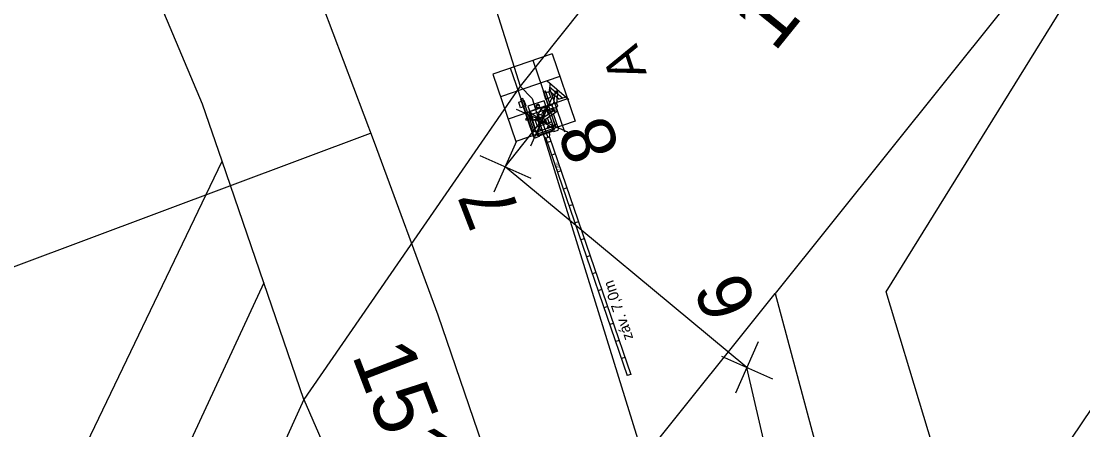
# Model space of a CAD drawing. Extents: x -553916 to -552953, y -1067470 to -1066637.
# Drawn here: x -553527.29 to -553497.63, y -1066980.55 to -1066969.15 of the extents above; entities that cross this region are included whole.
import ezdxf

# ---------------------------------------------------------------- set-up
doc = ezdxf.new("R2010")
doc.units = 0
for name, color, linetype in [('Default', 7, 'Continuous'), ('El2015-Ochrana podzemní', 7, 'Continuous'), ('El2015-Zabzař podzemní', 7, 'Continuous'), ('Hranice parcel', 7, 'Continuous'), ('Kolej', 7, 'Continuous'), ('Nová kabelizace', 7, 'Continuous'), ('nové prvky ZZ', 7, 'Continuous'), ('Parcelní čísla', 7, 'Continuous'), ('Propustek', 7, 'Continuous'), ('trasa_NN_popisky', 7, 'Continuous'), ('Vrstva 1', 7, 'Continuous')]:
    doc.layers.add(name, color=color, linetype=linetype)

# ---------------------------------------------------------------- blocks, each defined once
blk = doc.blocks.new('Křížek')
at = {"layer": 'El2015-Zabzař podzemní'}
for p, q in [((8.84, -8.84), (-8.84, 8.84)), ((8.84, -8.84), (-8.84, 8.84)), ((8.84, -8.84), (-8.84, 8.84)), ((8.84, 8.84), (-8.84, -8.84))]:
    blk.add_line(p, q, dxfattribs=at)

msp = doc.modelspace()

# ---------------------------------------------------------------- linework, layer by layer
at = {"layer": 'Hranice parcel'}
for p, q in [((-553499.93, -1066968.9), (-553506.23, -1066976.75)), ((-553520.52, -1066976.45), (-553530.98, -1066998.99)), ((-553519.4, -1066979.7), (-553528.66, -1067000.03))]:
    msp.add_line(p, q, dxfattribs=at)
for points in [[(-553489.9, -1066939.2), (-553506.21, -1066961.59), (-553507.62, -1066963.64), (-553510.49, -1066967.37), (-553513.35, -1066970.96)], [(-553481.25, -1066991.64), (-553501.02, -1066983.66), (-553503.13, -1066976.7), (-553485.37, -1066948.09)], [(-553533.63, -1066998.28), (-553526.12, -1066982.3), (-553521.68, -1066973.05)]]:
    msp.add_lwpolyline(points, dxfattribs=at)
at = {"layer": 'Kolej'}
msp.add_lwpolyline([(-553503.324, -1067065.808), (-553502.678, -1067054.027), (-553502.762, -1067041.504), (-553503.626, -1067029.057), (-553504.756, -1067019.974), (-553506.183, -1067011.388), (-553508.328, -1067001.388), (-553510.948, -1066991.622), (-553512.921, -1066985.291), (-553515.647, -1066977.347), (-553517.422, -1066972.53), (-553519.157, -1066967.95), (-553522.886, -1066958.375), (-553529.101, -1066942.549), (-553538.686, -1066918.107), (-553542.908, -1066907.329), (-553546.692, -1066897.676), (-553555.025, -1066876.441), (-553564.644, -1066851.894), (-553574.241, -1066827.427), (-553583.19, -1066804.618)], dxfattribs=at)
at = {"layer": 'Nová kabelizace'}
msp.add_line((-553505.478, -1066985.448), (-553507.017, -1066978.813), dxfattribs=at)
msp.add_lwpolyline([(-553507.017, -1066978.813), (-553513.769, -1066973.209), (-553512.749, -1066971.917)], dxfattribs=at)
at = {"layer": 'nové prvky ZZ'}
for p, q in [((-553512.461, -1066970.063), (-553514.116, -1066970.631)), ((-553512.349, -1066972.124), (-553512.993, -1066970.246)), ((-553512.461, -1066970.063), (-553511.816, -1066971.941)), ((-553514.116, -1066970.631), (-553513.471, -1066972.509)), ((-553512.975, -1066972.339), (-553513.62, -1066970.461)), ((-553512.246, -1066970.689), (-553513.901, -1066971.257)), ((-553512.595, -1066970.814), (-553511.991, -1066971.338)), ((-553512.52, -1066970.88), (-553512.54, -1066971.079)), ((-553512.7, -1066971.109), (-553512.644, -1066971.09)), ((-553512.56, -1066971.518), (-553512.7, -1066971.109)), ((-553512.504, -1066971.499), (-553512.644, -1066971.09)), ((-553512.54, -1066971.079), (-553512.261, -1066971.321)), ((-553512.53, -1066970.979), (-553512.163, -1066971.297)), ((-553512.528, -1066971.045), (-553512.119, -1066972.237)), ((-553512.385, -1066971.135), (-553512.421, -1066971.443)), ((-553512.293, -1066971.076), (-553512.4, -1066971.2)), ((-553512.355, -1066971.139), (-553512.338, -1066971.137)), ((-553512.345, -1066971.146), (-553512.348, -1066971.13)), ((-553512.306, -1066971.145), (-553512.341, -1066971.451)), ((-553512.031, -1066971.315), (-553513.686, -1066971.883)), ((-553513.282, -1066971.308), (-553513.337, -1066971.328)), ((-553512.971, -1066972.394), (-553513.337, -1066971.328)), ((-553512.964, -1066972.234), (-553513.282, -1066971.308)), ((-553513.106, -1066971.666), (-553512.624, -1066971.499)), ((-553513.05, -1066971.646), (-553512.624, -1066971.499)), ((-553512.91, -1066971.521), (-553512.912, -1066971.522)), ((-553512.875, -1066972.337), (-553512.624, -1066971.499)), ((-553512.453, -1066971.481), (-553512.775, -1066971.592)), ((-553512.393, -1066972.17), (-553512.624, -1066971.499)), ((-553512.066, -1066971.273), (-553512.261, -1066971.321)), ((-553512.875, -1066972.337), (-553513.105, -1066971.665)), ((-553513.105, -1066971.665), (-553512.393, -1066972.17)), ((-553513.079, -1066971.816), (-553513.058, -1066971.878)), ((-553513.056, -1066971.755), (-553513.007, -1066971.899)), ((-553513.043, -1066971.751), (-553512.993, -1066971.897)), ((-553512.775, -1066971.592), (-553512.853, -1066971.748)), ((-553512.853, -1066971.748), (-553512.811, -1066971.868)), ((-553512.853, -1066971.748), (-553512.757, -1066971.756)), ((-553512.8, -1066971.856), (-553512.763, -1066971.83)), ((-553512.775, -1066971.592), (-553512.713, -1066971.663)), ((-553512.759, -1066971.82), (-553512.743, -1066971.808)), ((-553512.713, -1066971.663), (-553512.757, -1066971.756)), ((-553512.757, -1066971.756), (-553512.734, -1066971.823)), ((-553512.73, -1066971.829), (-553512.746, -1066971.84)), ((-553512.743, -1066971.808), (-553512.73, -1066971.829)), ((-553512.736, -1066971.818), (-553512.591, -1066971.768)), ((-553512.731, -1066971.828), (-553512.628, -1066971.793)), ((-553512.731, -1066971.83), (-553512.725, -1066971.849)), ((-553512.377, -1066971.624), (-553512.717, -1066971.853)), ((-553512.713, -1066971.663), (-553512.427, -1066971.565)), ((-553512.336, -1066971.681), (-553512.677, -1066971.91)), ((-553512.609, -1066971.628), (-553512.567, -1066971.752)), ((-553512.587, -1066971.659), (-553512.557, -1066971.745)), ((-553512.557, -1066971.744), (-553512.552, -1066971.733)), ((-553512.496, -1066971.704), (-553512.531, -1066971.601)), ((-553512.47, -1066971.957), (-553512.522, -1066971.806)), ((-553512.506, -1066971.675), (-553512.469, -1066971.663)), ((-553512.445, -1066971.67), (-553512.476, -1066971.582)), ((-553512.383, -1066972.035), (-553512.472, -1066971.773)), ((-553512.469, -1066971.663), (-553512.461, -1066971.657)), ((-553512.461, -1066971.657), (-553512.454, -1066971.644)), ((-553512.422, -1066971.607), (-553512.434, -1066971.611)), ((-553512.411, -1066971.64), (-553512.423, -1066971.644)), ((-553512.421, -1066971.611), (-553512.422, -1066971.607)), ((-553512.278, -1066972.156), (-553512.422, -1066971.738)), ((-553512.414, -1066971.609), (-553512.421, -1066971.611)), ((-553512.414, -1066971.609), (-553512.405, -1066971.633)), ((-553512.405, -1066971.633), (-553512.412, -1066971.636)), ((-553512.412, -1066971.636), (-553512.411, -1066971.64)), ((-553511.816, -1066971.941), (-553513.471, -1066972.509)), ((-553513.201, -1066971.879), (-553513.194, -1066971.877)), ((-553513.201, -1066971.879), (-553513.192, -1066971.903)), ((-553513.195, -1066971.873), (-553513.183, -1066971.869)), ((-553513.194, -1066971.877), (-553513.195, -1066971.873)), ((-553513.192, -1066971.903), (-553513.185, -1066971.901)), ((-553513.185, -1066971.901), (-553513.184, -1066971.905)), ((-553513.184, -1066971.905), (-553513.172, -1066971.901)), ((-553513.134, -1066971.888), (-553513.147, -1066971.882)), ((-553513.124, -1066971.888), (-553513.134, -1066971.888)), ((-553513.087, -1066971.875), (-553513.124, -1066971.888)), ((-553513.021, -1066971.894), (-553512.944, -1066972.12)), ((-553513.007, -1066971.899), (-553512.995, -1066971.912)), ((-553512.995, -1066971.912), (-553512.977, -1066971.913)), ((-553512.993, -1066971.897), (-553512.98, -1066971.902)), ((-553512.98, -1066971.902), (-553512.819, -1066971.846)), ((-553512.977, -1066971.913), (-553512.815, -1066971.857)), ((-553512.944, -1066972.12), (-553512.874, -1066972.096)), ((-553512.871, -1066972.089), (-553512.936, -1066971.899)), ((-553512.907, -1066971.888), (-553512.898, -1066971.914)), ((-553512.898, -1066971.914), (-553512.891, -1066971.922)), ((-553512.895, -1066971.884), (-553512.885, -1066971.916)), ((-553512.891, -1066971.922), (-553512.882, -1066971.927)), ((-553512.885, -1066971.916), (-553512.876, -1066971.916)), ((-553512.882, -1066971.927), (-553512.873, -1066971.927)), ((-553512.876, -1066971.916), (-553512.85, -1066971.907)), ((-553512.876, -1066972.091), (-553512.871, -1066972.089)), ((-553512.874, -1066972.096), (-553512.876, -1066972.091)), ((-553512.873, -1066971.927), (-553512.84, -1066971.916)), ((-553512.871, -1066972.089), (-553512.546, -1066971.978)), ((-553512.851, -1066971.92), (-553512.83, -1066971.981)), ((-553512.842, -1066971.911), (-553512.819, -1066971.977)), ((-553512.717, -1066971.906), (-553512.782, -1066971.929)), ((-553512.769, -1066971.848), (-553512.757, -1066971.84)), ((-553512.76, -1066971.885), (-553512.738, -1066971.95)), ((-553512.745, -1066971.916), (-553512.754, -1066971.919)), ((-553512.748, -1066971.922), (-553512.751, -1066971.913)), ((-553512.749, -1066971.917), (-553512.585, -1066972.397)), ((-553512.71, -1066971.986), (-553512.674, -1066971.964)), ((-553512.693, -1066971.963), (-553512.681, -1066971.955)), ((-553512.658, -1066971.931), (-553512.677, -1066971.944)), ((-553512.673, -1066971.908), (-553512.668, -1066971.925)), ((-553512.664, -1066971.964), (-553512.645, -1066971.951)), ((-553512.663, -1066971.901), (-553512.656, -1066971.921)), ((-553512.645, -1066971.951), (-553512.658, -1066971.931)), ((-553512.546, -1066971.978), (-553512.589, -1066971.851)), ((-553512.541, -1066971.976), (-553512.546, -1066971.978)), ((-553512.539, -1066971.981), (-553512.541, -1066971.976)), ((-553512.47, -1066971.957), (-553512.539, -1066971.981)), ((-553512.468, -1066972.064), (-553512.349, -1066972.023)), ((-553512.456, -1066972.097), (-553512.468, -1066972.064)), ((-553512.349, -1066972.023), (-553512.319, -1066972.037)), ((-553512.998, -1066972.246), (-553513.012, -1066972.274)), ((-553512.879, -1066972.205), (-553512.998, -1066972.246)), ((-553512.942, -1066972.408), (-553512.971, -1066972.394)), ((-553512.823, -1066972.367), (-553512.942, -1066972.408)), ((-553512.867, -1066972.238), (-553512.879, -1066972.205)), ((-553512.875, -1066972.337), (-553512.393, -1066972.17)), ((-553512.829, -1066972.35), (-553512.823, -1066972.367)), ((-553512.548, -1066972.254), (-553512.705, -1066972.308)), ((-553512.538, -1066972.381), (-553512.632, -1066972.413)), ((-553512.632, -1066972.413), (-553510.36, -1066979.034)), ((-553512.538, -1066972.381), (-553510.266, -1066979.002)), ((-553512.418, -1066972.209), (-553512.412, -1066972.226)), ((-553512.412, -1066972.226), (-553512.293, -1066972.185)), ((-553512.293, -1066972.185), (-553512.278, -1066972.156)), ((-553512.593, -1066972.525), (-553512.499, -1066972.493)), ((-553512.375, -1066972.854), (-553512.469, -1066972.886)), ((-553512.213, -1066973.327), (-553512.307, -1066973.359)), ((-553512.051, -1066973.8), (-553512.145, -1066973.832)), ((-553511.889, -1066974.273), (-553511.983, -1066974.305)), ((-553511.726, -1066974.746), (-553511.82, -1066974.778)), ((-553511.564, -1066975.218), (-553511.658, -1066975.251)), ((-553511.402, -1066975.691), (-553511.496, -1066975.724)), ((-553511.239, -1066976.164), (-553511.333, -1066976.197)), ((-553511.077, -1066976.637), (-553511.171, -1066976.67)), ((-553510.915, -1066977.11), (-553511.009, -1066977.142)), ((-553510.753, -1066977.583), (-553510.847, -1066977.615)), ((-553510.59, -1066978.056), (-553510.684, -1066978.088)), ((-553510.428, -1066978.529), (-553510.522, -1066978.561)), ((-553510.266, -1066979.002), (-553510.36, -1066979.034))]:
    msp.add_line(p, q, dxfattribs=at)
for points in [[(-553512.696, -1066971.168), (-553512.643, -1066971.323), (-553512.497, -1066971.273), (-553512.55, -1066971.118)], [(-553513.248, -1066971.357), (-553513.195, -1066971.513), (-553513.341, -1066971.563), (-553513.395, -1066971.408)], [(-553513.136, -1066971.523), (-553513.056, -1066971.755), (-553512.606, -1066971.601), (-553512.686, -1066971.369)], [(-553513.111, -1066971.805), (-553513.076, -1066971.908), (-553513.063, -1066971.903), (-553513.098, -1066971.801)], [(-553513.069, -1066971.77), (-553513.053, -1066971.819), (-553513.036, -1066971.813), (-553513.053, -1066971.764)], [(-553512.867, -1066972.238), (-553512.829, -1066972.35), (-553512.418, -1066972.209), (-553512.456, -1066972.097)], [(-553512.848, -1066971.904), (-553512.851, -1066971.896), (-553512.833, -1066971.89), (-553512.83, -1066971.898)], [(-553512.811, -1066972.035), (-553512.806, -1066972.05), (-553512.784, -1066972.043), (-553512.789, -1066972.027)], [(-553512.649, -1066971.979), (-553512.644, -1066971.994), (-553512.621, -1066971.987), (-553512.627, -1066971.972)]]:
    msp.add_lwpolyline(points, close=True, dxfattribs=at)
for points in [[(-553512.869, -1066971.473), (-553512.92, -1066971.491), (-553512.91, -1066971.521), (-553512.858, -1066971.503), (-553512.865, -1066971.484)], [(-553512.912, -1066971.522), (-553512.896, -1066971.57), (-553512.802, -1066971.537), (-553512.82, -1066971.483), (-553512.86, -1066971.497)], [(-553512.865, -1066971.484), (-553512.838, -1066971.475), (-553512.841, -1066971.464), (-553512.869, -1066971.473)], [(-553513.079, -1066971.816), (-553513.091, -1066971.82), (-553513.07, -1066971.882), (-553513.058, -1066971.878)], [(-553513.065, -1066971.783), (-553513.088, -1066971.791), (-553513.079, -1066971.816)], [(-553513.058, -1066971.878), (-553513.049, -1066971.904), (-553513.017, -1066971.893), (-553513.043, -1066971.815)], [(-553512.754, -1066971.845), (-553512.772, -1066971.818), (-553512.764, -1066971.813), (-553512.743, -1066971.845)], [(-553512.582, -1066971.618), (-553512.57, -1066971.653), (-553512.587, -1066971.659), (-553512.599, -1066971.624)], [(-553512.526, -1066971.724), (-553512.552, -1066971.733), (-553512.579, -1066971.656)], [(-553512.559, -1066971.61), (-553512.551, -1066971.635)], [(-553512.551, -1066971.635), (-553512.534, -1066971.629), (-553512.512, -1066971.691), (-553512.53, -1066971.697)], [(-553512.506, -1066971.711), (-553512.54, -1066971.609), (-553512.53, -1066971.606), (-553512.496, -1066971.704)], [(-553512.53, -1066971.697), (-553512.521, -1066971.721)], [(-553512.44, -1066971.667), (-553512.446, -1066971.669), (-553512.467, -1066971.606), (-553512.458, -1066971.602), (-553512.454, -1066971.614)], [(-553512.454, -1066971.614), (-553512.435, -1066971.607), (-553512.434, -1066971.611)], [(-553512.423, -1066971.644), (-553512.421, -1066971.648), (-553512.44, -1066971.654)], [(-553512.44, -1066971.654), (-553512.436, -1066971.665)], [(-553513.166, -1066971.858), (-553513.185, -1066971.864), (-553513.183, -1066971.869)], [(-553513.172, -1066971.901), (-553513.171, -1066971.905), (-553513.152, -1066971.899)], [(-553513.152, -1066971.899), (-553513.148, -1066971.91), (-553513.139, -1066971.907), (-553513.16, -1066971.843), (-553513.17, -1066971.847), (-553513.166, -1066971.858)], [(-553512.827, -1066971.9), (-553512.828, -1066971.897), (-553512.853, -1066971.906), (-553512.85, -1066971.914), (-553512.828, -1066971.906)], [(-553512.806, -1066971.973), (-553512.846, -1066971.986), (-553512.843, -1066971.995), (-553512.799, -1066971.98), (-553512.799, -1066971.98)], [(-553512.798, -1066971.98), (-553512.835, -1066971.993), (-553512.82, -1066972.038), (-553512.781, -1066972.025), (-553512.796, -1066971.982)], [(-553512.684, -1066971.949), (-553512.666, -1066971.977), (-553512.659, -1066971.971), (-553512.68, -1066971.939)], [(-553512.68, -1066971.94), (-553512.662, -1066971.934)], [(-553512.658, -1066971.932), (-553512.625, -1066971.921), (-553512.628, -1066971.911), (-553512.678, -1066971.928)], [(-553512.66, -1066971.973), (-553512.657, -1066971.982), (-553512.619, -1066971.969), (-553512.634, -1066971.924)], [(-553512.567, -1066972.095), (-553512.562, -1066972.093), (-553512.55, -1066972.129), (-553512.578, -1066972.139), (-553512.59, -1066972.103), (-553512.585, -1066972.101)], [(-553512.585, -1066972.101), (-553512.588, -1066972.093), (-553512.57, -1066972.087), (-553512.567, -1066972.095)], [(-553512.766, -1066972.163), (-553512.761, -1066972.161), (-553512.749, -1066972.197), (-553512.776, -1066972.207), (-553512.789, -1066972.171), (-553512.784, -1066972.169)], [(-553512.784, -1066972.169), (-553512.787, -1066972.161), (-553512.769, -1066972.155), (-553512.766, -1066972.163)], [(-553512.632, -1066972.413), (-553512.683, -1066972.367), (-553512.703, -1066972.307)], [(-553512.538, -1066972.381), (-553512.526, -1066972.313), (-553512.546, -1066972.253)]]:
    msp.add_lwpolyline(points, dxfattribs=at)
for centre, radius in [((-553512.347, -1066971.138), 0.00856), ((-553512.386, -1066971.506), 0.0716), ((-553512.356, -1066971.653), 0.0347), ((-553512.749, -1066971.917), 0.0725)]:
    msp.add_circle(centre, radius, dxfattribs=at)
for centre, radius, start, end in [((-553512.345, -1066971.14), 0.0399, 353.2567, 174.9637), ((-553512.749, -1066971.917), 0.0795, 129.387, 299.921)]:
    msp.add_arc(centre, radius, start, end, dxfattribs=at)
at = {"layer": 'Propustek'}
msp.add_lwpolyline([(-553576.56, -1066984.514), (-553536.119, -1066969.402), (-553529.408, -1066976.709), (-553517.537, -1066972.276)], dxfattribs=at)
at = {"layer": 'trasa_NN_popisky'}
msp.add_lwpolyline([(-553456.479, -1066963.507), (-553494.623, -1066975.849), (-553504.368, -1066990.297)], dxfattribs=at)
at = {"layer": 'Vrstva 1'}
for p, q in [((-553514.13, -1066968.51), (-553513.35, -1066970.96)), ((-553513.35, -1066970.96), (-553519.4, -1066979.7)), ((-553520.52, -1066976.45), (-553521.68, -1066973.05)), ((-553519.4, -1066979.7), (-553520.52, -1066976.45)), ((-553509.91, -1066981.33), (-553506.23, -1066976.75)), ((-553506.23, -1066976.75), (-553504.27, -1066984.05)), ((-553519.4, -1066979.7), (-553514.85, -1066990.05))]:
    msp.add_line(p, q, dxfattribs=at)
for points in [[(-553521.68, -1066973.05), (-553522.23, -1066971.46), (-553527.43, -1066959.15)], [(-553513.35, -1066970.96), (-553513.02, -1066971.31), (-553509.91, -1066981.33)]]:
    msp.add_lwpolyline(points, dxfattribs=at)

# ---------------------------------------------------------------- block references
at = {"layer": 'El2015-Ochrana podzemní', "xscale": 0.06250000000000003, "yscale": 0.0625, "rotation": 111.13806774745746}
for p in [(-553512.749, -1066971.917), (-553513.769, -1066973.209), (-553507.017, -1066978.813)]:
    msp.add_blockref('Křížek', p, dxfattribs=at)

# ---------------------------------------------------------------- texts
at = {"layer": 'Default'}
for s, p in [('8', (-553510.54, -1066972.73)), ('7', (-553513.318, -1066974.547)), ('6', (-553506.723, -1066977.105))]:
    msp.add_text(s, height=1.5, rotation=111.1381, dxfattribs=at).set_placement(p)
at = {"layer": 'nové prvky ZZ'}
for s, height, rotation, p in [('A', 1.025, 108.8917, (-553509.813, -1066970.609)), ('265', 0.025, 108.9398, (-553512.773, -1066971.948)), ('7,00m', 0.0646, 108.9398, (-553512.243, -1066973.303)), ('záv. 7,0m', 0.3, 109.138, (-553510.19, -1066977.993))]:
    msp.add_text(s, height=height, rotation=rotation, dxfattribs=at).set_placement(p)
at = {"layer": 'Parcelní čísla'}
msp.add_text('1517/1', height=1.7, rotation=51, dxfattribs=at).set_placement((-553506.254, -1066970.044))
at = {"layer": 'Vrstva 1'}
msp.add_text('1517/8', height=1.7, rotation=290.9878, dxfattribs=at).set_placement((-553518.068, -1066978.458))

doc.saveas('drawing.dxf')
